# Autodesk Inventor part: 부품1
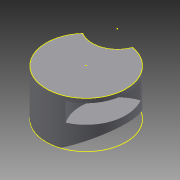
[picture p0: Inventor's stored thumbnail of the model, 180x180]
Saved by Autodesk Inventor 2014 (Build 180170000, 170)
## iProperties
Created: 2015-12
Part Number: 부품1
Material: 일반
Document SubType Name: Modeling
Designer: ok
Density: 1 g/cm^3
Appearance: 기본값
Author: ok
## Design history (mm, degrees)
sketch "스케치1"
  geometry: C1 r 72.5 at (0, 0); 1 further point
  constraints: 1 centre point, 1 coincident
  dimensions: "d0" = 145 diameter of C1
extrude "돌출1" new body sketch "스케치1" distance "d1" = 84; taper "d2" = 0 deg
sketch "스케치2"
  geometry: C1 r 72.5 at (0, 0) reference; C2 r 46 at (-30, 87)
  constraints: 1 centre point
  dimensions: "d5" = 30 horizontal distance of C1.centre C2.centre; "d6" = 87 vertical distance of C1.centre C2.centre; "d7" = 92 diameter of C2
extrude "돌출2" cut sketch "스케치2" stored distance "d8" = 0; taper "d9" = 0 deg
node "작업 평면1"
sketch "스케치3"
  geometry: A1 r 46 centre (-30, 87) between (-54.355, 47.977) and (13.231, 71.282) reference; A2 r 72.5 centre (0, 0) between (-54.355, 47.977) and (13.231, 71.282) reference
sketch "스케치4"
  geometry: 1 further point
sketch "스케치5"
  geometry: 1 further point
sketch "스케치6"
  geometry: A1 r 46 centre (-30, 87) between (-54.355, 47.977) and (13.231, 71.282) reference; A2 r 72.5 centre (0, 0) between (-54.355, 47.977) and (13.231, 71.282) reference
sketch "스케치7"
  geometry: A1 r 68 centre (-85, -27) between (-29.466, -66.242) and (-62.291, 37.096); A2 r 46 centre (30, 87) between (-13.231, 71.282) and (54.355, 47.977) reference; A3 r 72.5 centre (0, 0) between (-13.231, 71.282) and (54.355, 47.977) reference; A4 r 72.5 centre (0, 0) between (-62.291, 37.096) and (-29.466, -66.242); 1 further point
  constraints: 6 point on circle, 2 centre point, 1 concentric
  dimensions: "d10" = 136 diameter of A1; "d11" = 27 vertical distance of A1.centre point (0, 0); "d12" = 85 horizontal distance of A1.centre point (0, 0)
extrude "돌출3" cut sketch "스케치7" distance "d13" = 34; taper "d14" = 0 deg
sketch "스케치8"
  geometry: A1 r 46 centre (30, 87) between (-13.231, 71.282) and (54.355, 47.977) reference; A2 r 72.5 centre (0, 0) between (-13.231, 71.282) and (54.355, 47.977) reference
sketch "스케치9"
  geometry: 1 further point
sketch "스케치10"
  geometry: L1 (-10.944, -6.672)-(-84.341, 35.704); L2 (-72.5, 0)-(72.5, 0) reference; L3 (-72.5, 0)-(-72.5, 84) reference; 4 further points
  constraints: 2 end point, 2 point on line
  dimensions: "d15" = 50 distance of L3.start point (-22.5, 0); "d16" = 30 deg angle of L2 L1
extrude "돌출4" cut sketch "스케치10" stored distance "d18" = 34; taper "d19" = 0 deg
sketch "스케치11" dims "d20" = 30
  geometry: L1 (21, -9)-(35.266, -19.365); L2 (35.266, -19.365)-(29.817, -36.135); L3 (29.817, -36.135)-(12.183, -36.135); L4 (12.183, -36.135)-(6.734, -19.365); L5 (6.734, -19.365)-(21, -9); 3 further points
  constraints: 10 end point, 1 coincident, 1 vertical alignment, 13 other
  dimensions: "d21" = 21 horizontal distance of point (21, -24) point (0, 0); "d22" = 24 vertical distance of point (21, -24) point (0, 0)
extrude "돌출5" cut sketch "스케치11" distance "d23" = 38; taper "d24" = 0 deg
sketch "스케치12"
  geometry: A1 r 46 centre (-30, 87) between (-54.355, 47.977) and (13.231, 71.282) reference; A2 r 72.5 centre (0, 0) between (-54.355, 47.977) and (13.231, 71.282) reference
node "솔리드1"
node "투영된 루프1"
other parameters: "d17" = 34
